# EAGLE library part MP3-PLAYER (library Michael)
Modified MP3 Player
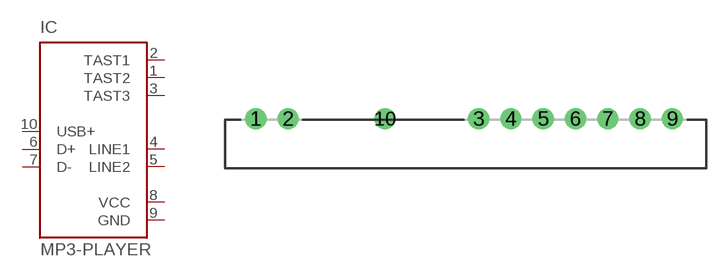
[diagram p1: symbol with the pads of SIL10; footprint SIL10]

Designator prefix IC

## MP3-PLAYER  [SIL10]
1  TAST2  in
2  TAST1  in
3  TAST3  out
4  LINE1  out
5  LINE2  out
6  D+
7  D-
8  VCC  pwr
9  GND  pwr
10  USB+

## Footprint SIL10 (pad centres in mm)
Single In line 10 leads ER Receiver Source: http://www.lprs.co.uk/pdf_directory/2386mylprs1132229147er-datasheet-2.3-sept-05.pdf
drill 1 pad 1.676 round: 1 -16.51,2.54; 2 -13.97,2.54; 3 1.03,2.54; 4 3.57,2.54; 5 6.11,2.54; 6 8.65,2.54; 7 11.19,2.54; 8 13.73,2.54; 9 16.27,2.54; 10 -6.35,2.54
